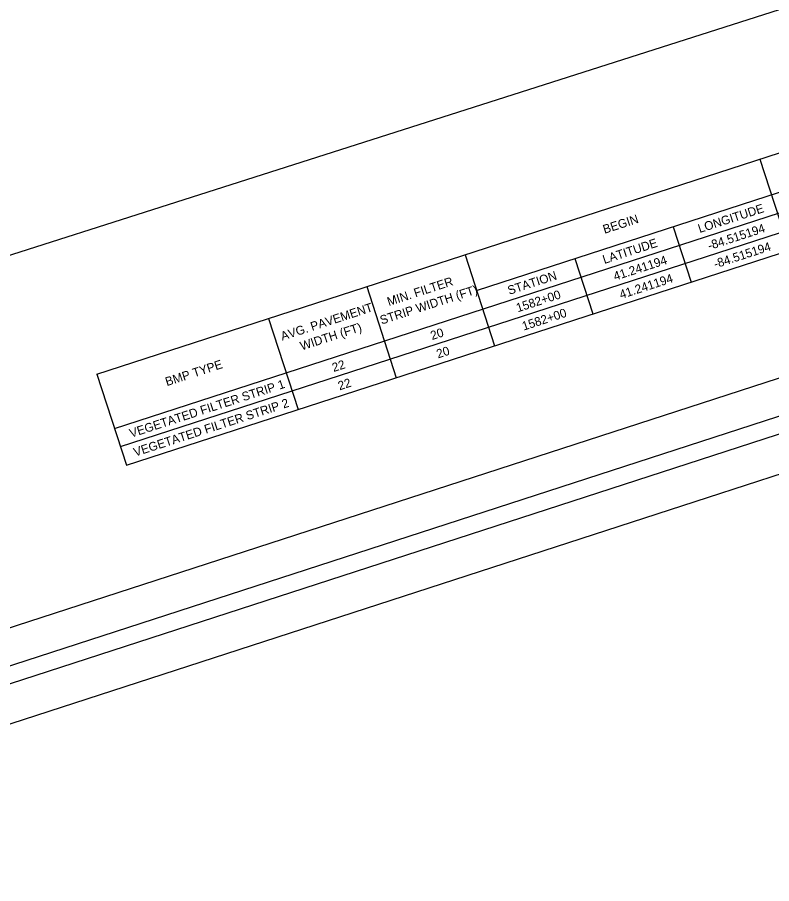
# Model space of a CAD drawing. Extents: x -468563856 to 36492962, y -306094093 to 11899197.
# Drawn here: x 1821405 to 1824382, y 526900 to 530321 of the extents above; entities that cross this region are included whole.
import ezdxf

# ---------------------------------------------------------------- set-up
doc = ezdxf.new("R2010")
doc.units = 0
for name, color, linetype in [('Default', 7, 'Continuous'), ('Level 63', 7, 'Continuous'), ('SC_Scratch1', 7, 'Continuous'), ('SH_Border', 7, 'Continuous'), ('SH_Cut_Line', 7, 'Continuous')]:
    doc.layers.add(name, color=color, linetype=linetype)

msp = doc.modelspace()

# ---------------------------------------------------------------- linework, layer by layer
at = {"layer": 'Default'}
for p, q in [((1821719.1, 528911.4), (1825886.6, 530264.4)), ((1821788.9, 528696.4), (1825956.4, 530049.4)), ((1823217.5, 529242), (1825544.5, 529997.5)), ((1821811.8, 528625.8), (1825979.3, 529978.8)), ((1821835.8, 528551.8), (1826003.3, 529904.8)), ((1824335.2, 529760.8), (1824452, 529401.1)), ((1823993.2, 529493.8), (1824064.1, 529275.2)), ((1823171.7, 529383), (1823288.5, 529023.4)), ((1823605.3, 529367.9), (1823676.3, 529149.3)), ((1822783.9, 529257.1), (1822900.6, 528897.5)), ((1822396, 529131.2), (1822512.8, 528771.6)), ((1821719.1, 528911.4), (1821835.8, 528551.8))]:
    msp.add_line(p, q, dxfattribs=at)
at = {"layer": 'Level 63'}
for points in [[(1817088.6, 533305.9), (1826789.4, 536455.4), (1828827.2, 530178.6), (1819126.4, 527029.2)], [(1819195.4, 527203), (1828668.6, 530278.5), (1826708.4, 536316.3), (1817235.1, 533240.7)]]:
    msp.add_lwpolyline(points, close=True, dxfattribs=at)
at = {"layer": 'SC_Scratch1'}
msp.add_lwpolyline([(1818754.7, 531265.4), (1818680.3, 532626), (1826365, 535120.9), (1826839.3, 533890.3), (1827446.9, 532018.9), (1827532.1, 531348.3), (1819682.5, 528840.1), (1819362.2, 529394.3)], close=True, dxfattribs=at)
at = {"layer": 'SH_Border'}
msp.add_lwpolyline([(1817866.1, 533173.3), (1826996.9, 536137.7), (1828942.3, 530145.6), (1819811.4, 527181.2)], close=True, dxfattribs=at)
at = {"layer": 'SH_Cut_Line'}
msp.add_lwpolyline([(1819429.8, 526899.6), (1829131.3, 530049.3), (1827093.3, 536326.7), (1817391.7, 533177)], close=True, dxfattribs=at)

# ---------------------------------------------------------------- texts
at = {"layer": 'Default'}
for s, p in [('LONGITUDE', (1824097.9, 529468.7)), ('BEGIN', (1823722.5, 529465.7)), ('-84.515194', (1824136.1, 529401.2)), ('LATITUDE', (1823721.6, 529346.5)), ('-84.515194', (1824159.5, 529328.9)), ('41.241194', (1823764.1, 529280.4)), ('STATION', (1823346.4, 529224.7)), ('41.241194', (1823787.6, 529208.1)), ('MIN. FILTER ', (1822871, 529180.2)), ('STRIP WIDTH (FT)', (1822842.6, 529107.2)), ('1582+00', (1823380, 529155.7)), ('AVG. PAVEMENT ', (1822450.7, 529043.8)), ('1582+00', (1823403.4, 529083.4)), ('WIDTH (FT)', (1822527.5, 529004.9)), ('20', (1823041.9, 529046)), ('20', (1823065.4, 528973.7)), ('BMP TYPE', (1821995.1, 528863.9)), ('22', (1822653.2, 528919.8)), ('22', (1822676.7, 528847.5)), ('VEGETATED FILTER STRIP 1', (1821853.9, 528660.3)), ('VEGETATED FILTER STRIP 2', (1821870, 528585.6))]:
    msp.add_text(s, height=34.66, rotation=17.9864, dxfattribs=at).set_placement(p)

doc.saveas('drawing.dxf')
